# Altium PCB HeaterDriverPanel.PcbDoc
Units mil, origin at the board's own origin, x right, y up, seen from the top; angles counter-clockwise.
Board outline 14150 x 4775 mil, 6 copper layers (Top Layer, GND1, P, N, GND2, Bottom Layer), stack 62.668 mil thick; 0 components, 0 nets, 30 pads, 0 vias.
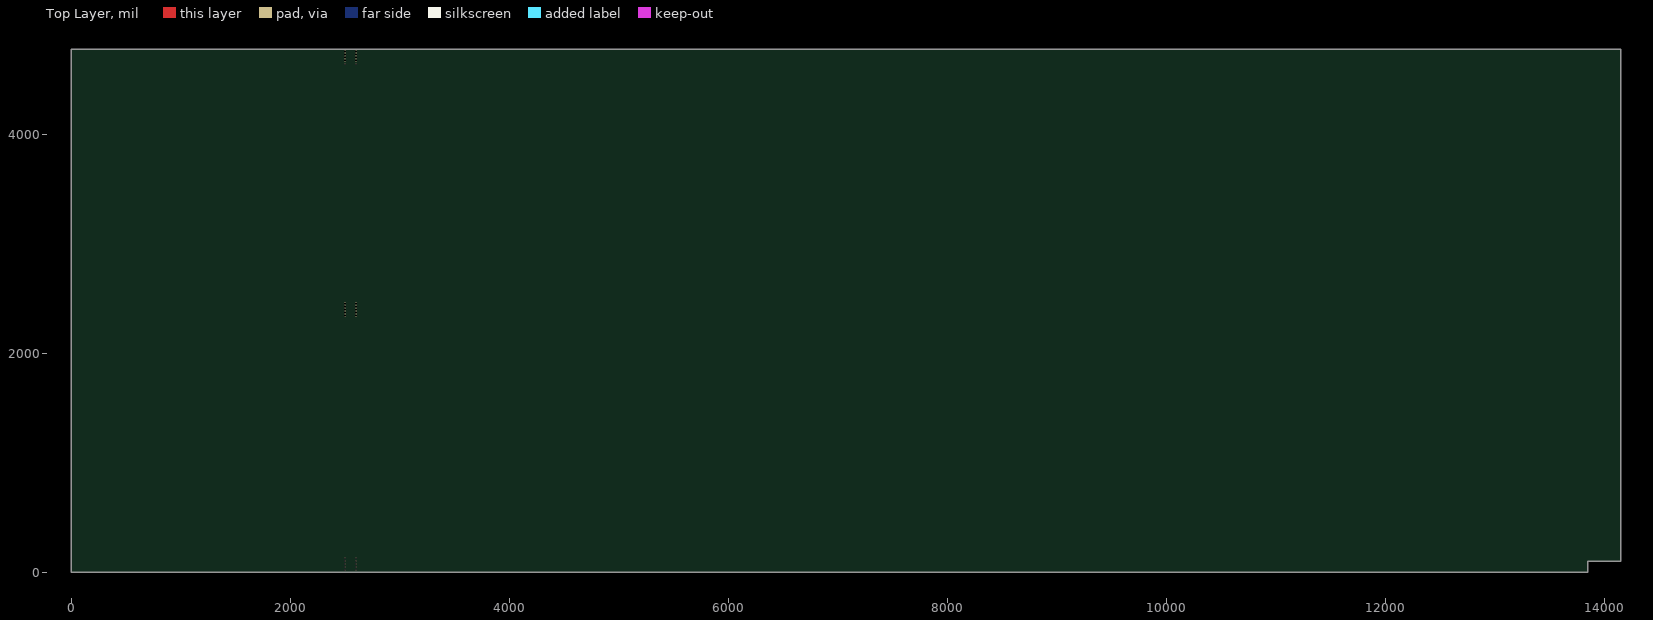
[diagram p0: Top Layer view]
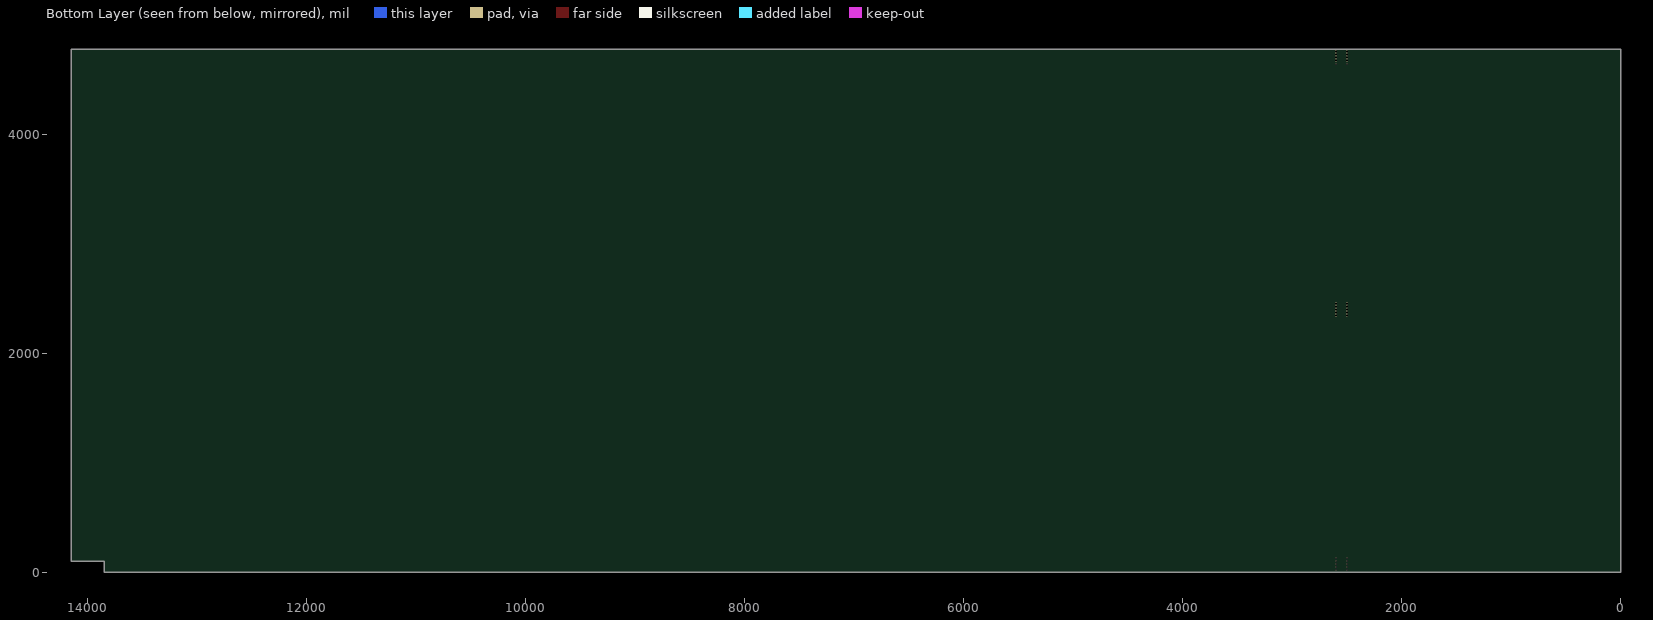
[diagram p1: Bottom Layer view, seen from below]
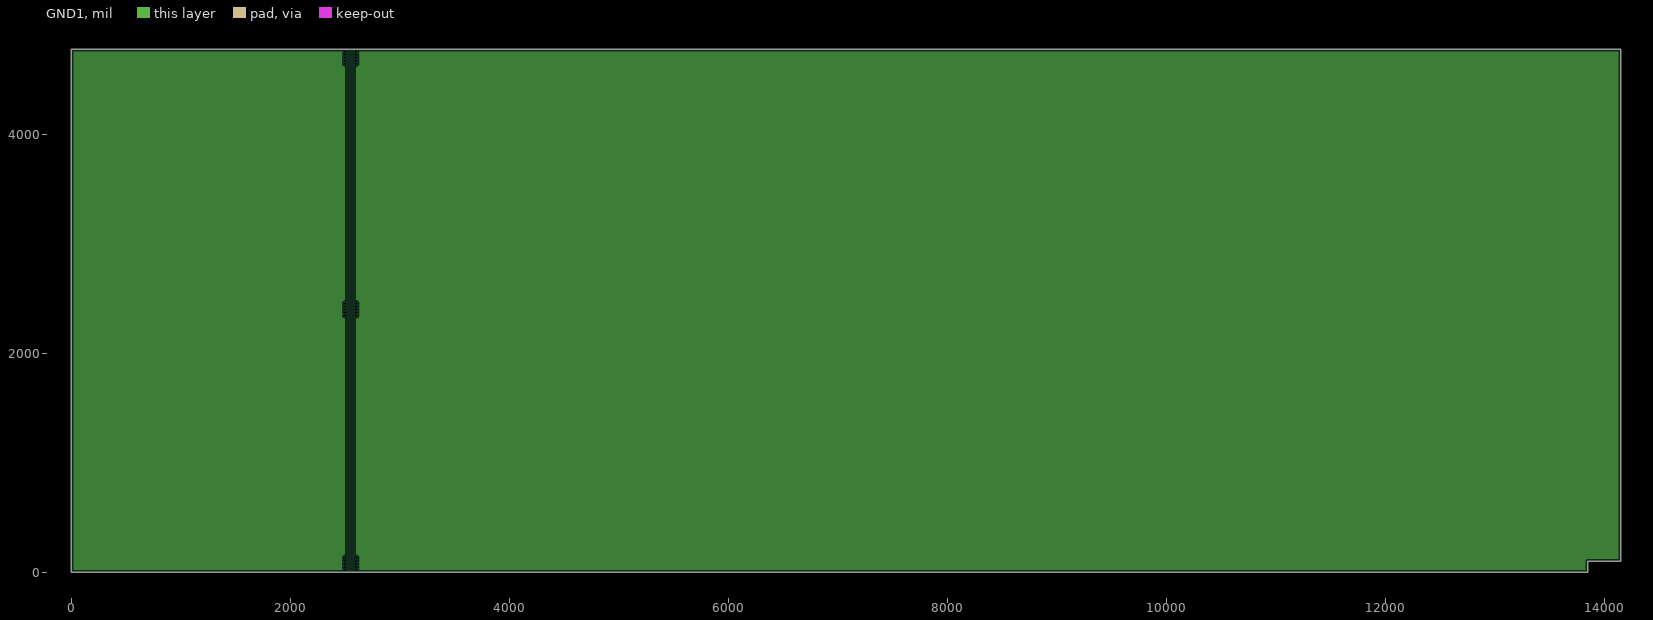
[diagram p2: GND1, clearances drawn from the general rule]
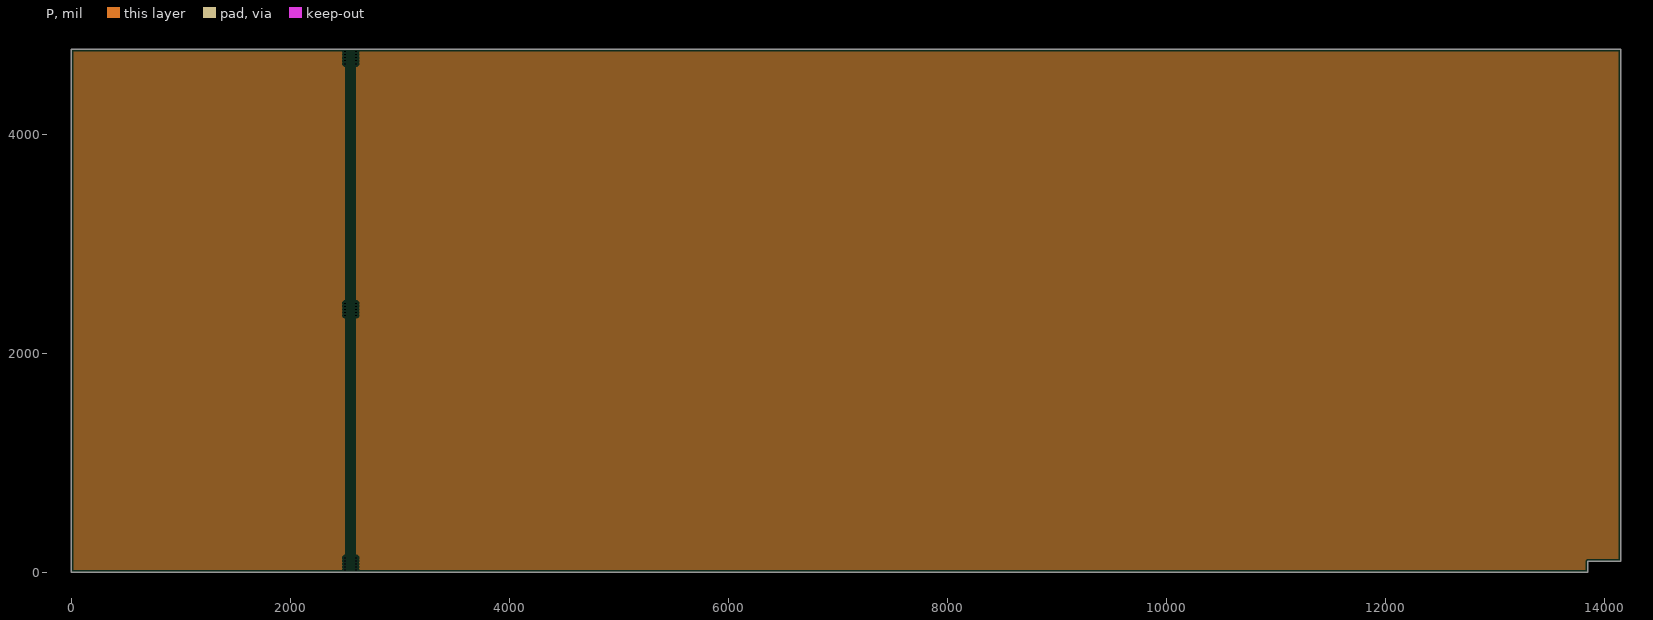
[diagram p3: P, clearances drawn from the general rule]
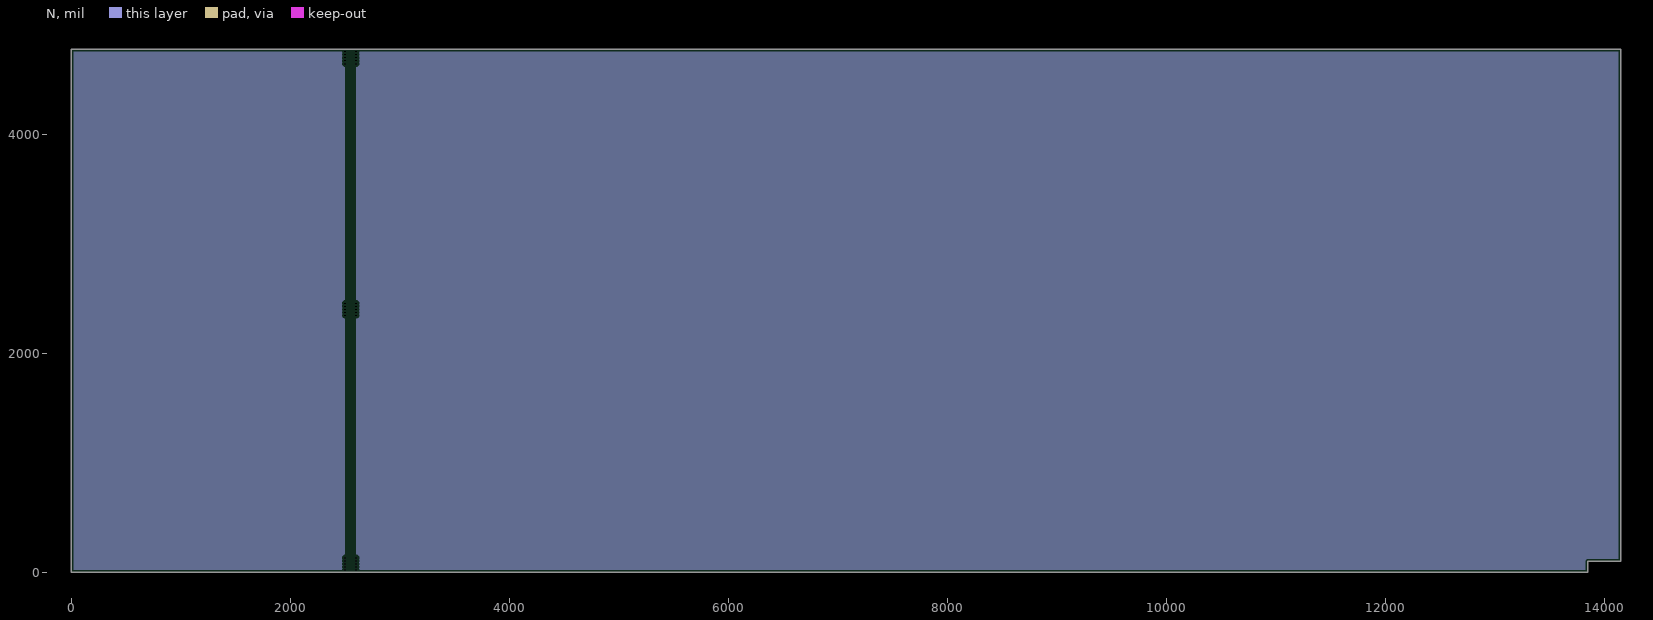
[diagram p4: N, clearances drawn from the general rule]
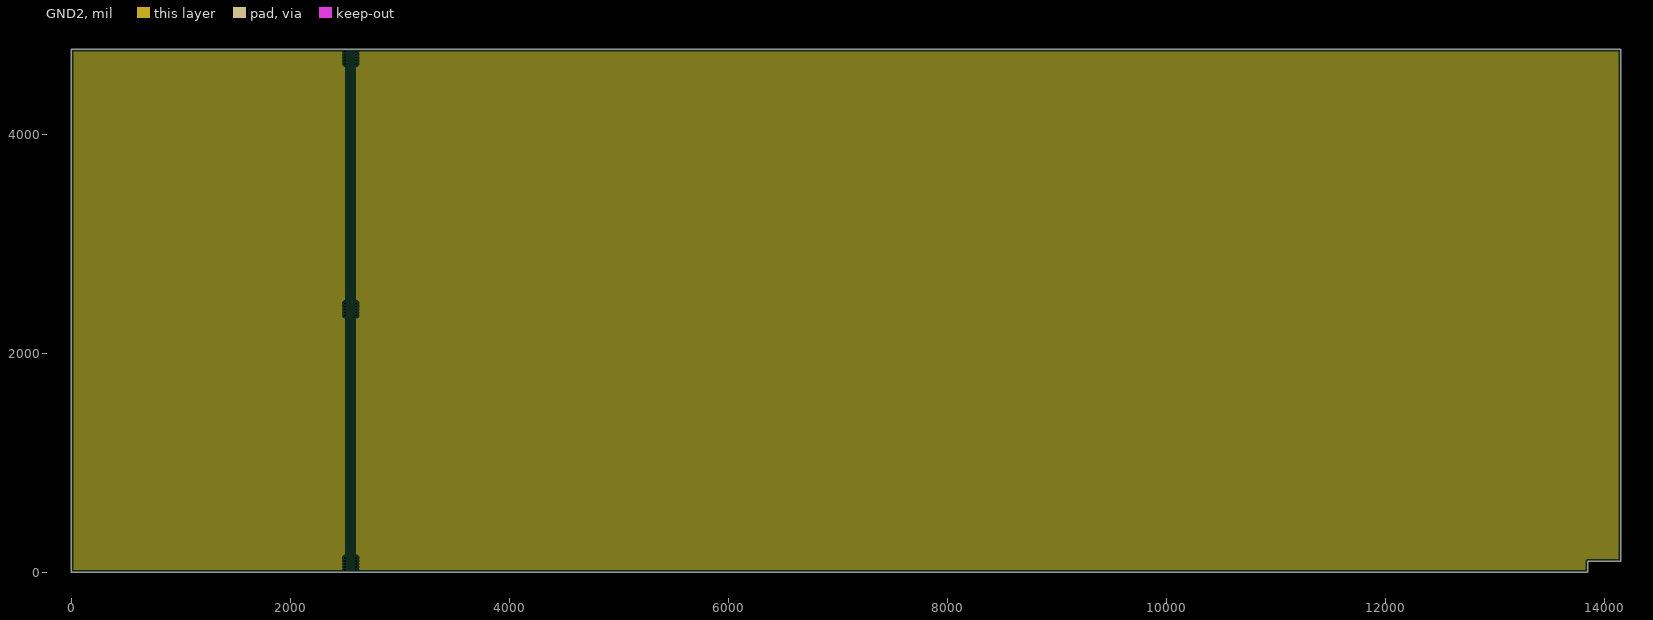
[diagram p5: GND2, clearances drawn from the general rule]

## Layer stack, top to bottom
Top Solder: solder mask 1, Solder Resist, Dk 3.5
Top Layer: signal copper 2.4
Dielectric 1: prepreg 2.8, PP-006, Dk 4.1
GND1: plane copper 1.417
Dielectric 2: core 21, Core-037, Dk 4.8
P: plane copper 1.417
Dielectric 3: prepreg 4.6, PP-016, Dk 4.4
N: plane copper 1.417
Dielectric 4: core 21, Core-037, Dk 4.8
GND2: plane copper 1.417
Dielectric 5: prepreg 2.8, PP-006, Dk 4.1
Bottom Layer: signal copper 2.4
Bottom Solder: solder mask 1, Solder Resist, Dk 3.5

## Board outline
0,0 0,4775 14150,4775 14150,100 13850,100 13850,0

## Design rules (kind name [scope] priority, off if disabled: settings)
Clearance [All] p1: gap=10 ignorepadtopadclearanceinfootprint=FALSE
PlaneClearance [All] p1: clearance=20
PlaneConnect [All] p1: planeconnectstyle=Relief reliefexpansion=20 reliefentries=4 reliefconductorwidth=10 reliefairgap=10
PolygonConnect [All] p1: connectstyle=Relief reliefconductorwidth=10 reliefentries=4 polygonreliefangle="90 Angle" airgapwidth=10
RoutingVias [All] p1: holewidth=28 width=50 viastyle="Through Hole" minholewidth=28 minwidth=50 maxholewidth=28 maxwidth=50
SolderMaskExpansion [All] p1: expansion=4 istentingtop=FALSE
Width [All] p1: maxlimit=10 minlimit=10 preferedwidth=10
28 further rules are at their usual default settings.

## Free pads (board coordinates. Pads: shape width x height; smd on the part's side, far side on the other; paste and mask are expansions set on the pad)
  round 18 hole 18 unplated mask+0: 0(2500,19) 0(2500,47) 0(2500,75) 0(2500,103) 0(2500,131) 0(2500,2344) 0(2500,2372) 0(2500,2400) 0(2500,2428) 0(2500,2456) 0(2500,4644) 0(2500,4672) 0(2500,4700) 0(2500,4728) 0(2500,4756) 0(2600,19) 0(2600,47) 0(2600,75) 0(2600,103) 0(2600,131) 0(2600,2344) 0(2600,2372) 0(2600,2400) 0(2600,2428) 0(2600,2456) 0(2600,4644) 0(2600,4672) 0(2600,4700) 0(2600,4728) 0(2600,4756)

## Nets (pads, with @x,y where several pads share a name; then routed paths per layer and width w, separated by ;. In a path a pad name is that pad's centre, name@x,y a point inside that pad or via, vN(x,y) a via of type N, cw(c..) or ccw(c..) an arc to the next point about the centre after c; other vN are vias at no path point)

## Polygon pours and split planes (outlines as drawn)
no net on GND1 (split plane): 2499.92,20.1 20.1,20.1 20.1,4754.9 2499.92,4754.9
no net on GND1 (split plane): 14129.9,120.1 13850,120.1 13846.08,119.71 13842.31,118.57 13838.83,116.71 13835.79,114.21 13833.29,111.17 13831.43,107.69 13830.29,103.92 13829.9,100 13829.9,20.1 2600.08,20.1 2600.08,4754.9 14129.9,4754.9
no net on P (split plane): 2499.92,20.1 20.1,20.1 20.1,4754.9 2499.92,4754.9
no net on P (split plane): 14129.9,120.1 13850,120.1 13846.08,119.71 13842.31,118.57 13838.83,116.71 13835.79,114.21 13833.29,111.17 13831.43,107.69 13830.29,103.92 13829.9,100 13829.9,20.1 2600.08,20.1 2600.08,4754.9 14129.9,4754.9
no net on N (split plane): 2499.92,20.1 20.1,20.1 20.1,4754.9 2499.92,4754.9
no net on N (split plane): 14129.9,120.1 13850,120.1 13846.08,119.71 13842.31,118.57 13838.83,116.71 13835.79,114.21 13833.29,111.17 13831.43,107.69 13830.29,103.92 13829.9,100 13829.9,20.1 2600.08,20.1 2600.08,4754.9 14129.9,4754.9
no net on GND2 (split plane): 2499.92,20.1 20.1,20.1 20.1,4754.9 2499.92,4754.9
no net on GND2 (split plane): 14129.9,120.1 13850,120.1 13846.08,119.71 13842.31,118.57 13838.83,116.71 13835.79,114.21 13833.29,111.17 13831.43,107.69 13830.29,103.92 13829.9,100 13829.9,20.1 2600.08,20.1 2600.08,4754.9 14129.9,4754.9

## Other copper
GND1 (plane layer: these items are gaps in the copper):
  lines w100: 2550,0 2550,4775
P (plane layer: these items are gaps in the copper):
  lines w100: 2550,0 2550,4775
N (plane layer: these items are gaps in the copper):
  lines w100: 2550,0 2550,4775
GND2 (plane layer: these items are gaps in the copper):
  lines w100: 2550,0 2550,4775

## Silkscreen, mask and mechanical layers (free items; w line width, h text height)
Mechanical 1:
  lines w10: 0,0 13850,0 ; 0,0 0,4775 ; 0,0 2500,0 2500,4775 0,4775 ; 0,4775 14150,4775 ; 13850,0 13850,100 14150,100 14150,4775 ; 13850,0 2600,0 2600,4775 14150,4775
Route Tool Path:
  lines w100: 2550,175 2550,2300 ; 2550,2500 2550,4600
Drill Drawing:
  drawing of 157 lines, arcs and shapes, not listed
  text "Symbol" at 97.5,7952.5 h72
  text "Count" at 603.38,7952.5 h72
  text "Hole Size" at 1203.22,7952.5 h72
  text "Plated" at 2352.88,7952.5 h72
  text "Hole Type" at 2858.76,7952.5 h72
  text "Drill Layer Pair" at 3592.56,7952.5 h72
  text "Via/Pad" at 5092.11,7952.5 h72
  text "Pad Shape" at 5681.96,7952.5 h72
  text "Template" at 6427.76,7952.5 h72
  text "Description" at 7117.57,7952.5 h72
  text "Hole Tolerance (+)" at 7971.33,7952.5 h72
  text "Hole Tolerance (-)" at 9304.94,7952.5 h72
  text "2" at 603.38,7802.5 h60
  text "75.00mil (1.905mm)" at 1203.22,7802.5 h60
  text "PTH" at 2352.88,7802.5 h60
  text "Round" at 2858.76,7802.5 h60
  text "Top Layer - Bottom Layer" at 3592.56,7802.5 h60
  text "Pad" at 5092.11,7802.5 h60
  text "Rounded" at 5681.96,7802.5 h60
  text "c254h190" at 6427.76,7802.5 h60
  text "2" at 603.38,7652.5 h60
  text "155.00mil (3.937mm)" at 1203.22,7652.5 h60
  text "PTH" at 2352.88,7652.5 h60
  text "Round" at 2858.76,7652.5 h60
  text "Top Layer - Bottom Layer" at 3592.56,7652.5 h60
  text "Pad" at 5092.11,7652.5 h60
  text "Rounded" at 5681.96,7652.5 h60
  text "c508h394" at 6427.76,7652.5 h60
  text "4" at 603.38,7502.5 h60
  text "29.00mil (0.737mm)" at 1203.22,7502.5 h60
  text "PTH" at 2352.88,7502.5 h60
  text "Round" at 2858.76,7502.5 h60
  text "Top Layer - Bottom Layer" at 3592.56,7502.5 h60
  text "Pad" at 5092.11,7502.5 h60
  text "Rounded" at 5681.96,7502.5 h60
  text "c120h74" at 6427.76,7502.5 h60
  text "4" at 603.38,7352.5 h60
  text "128.35mil (3.260mm)" at 1203.22,7352.5 h60
  text "PTH" at 2352.88,7352.5 h60
  text "Round" at 2858.76,7352.5 h60
  text "Top Layer - Bottom Layer" at 3592.56,7352.5 h60
  text "Pad" at 5092.11,7352.5 h60
  text "Rounded" at 5681.96,7352.5 h60
  text "c476h326" at 6427.76,7352.5 h60
  text "4" at 603.38,7202.5 h60
  text "190.00mil (4.826mm)" at 1203.22,7202.5 h60
  text "PTH" at 2352.88,7202.5 h60
  text "Round" at 2858.76,7202.5 h60
  text "Top Layer - Bottom Layer" at 3592.56,7202.5 h60
  text "Pad" at 5092.11,7202.5 h60
  text "Rounded" at 5681.96,7202.5 h60
  text "c559h483" at 6427.76,7202.5 h60
  text "4" at 603.38,7052.5 h60
  text "193.00mil (4.902mm)" at 1203.22,7052.5 h60
  text "PTH" at 2352.88,7052.5 h60
  text "Round" at 2858.76,7052.5 h60
  text "Top Layer - Bottom Layer" at 3592.56,7052.5 h60
  text "Pad" at 5092.11,7052.5 h60
  text "Rounded" at 5681.96,7052.5 h60
  text "c584h490" at 6427.76,7052.5 h60
  text "8" at 603.38,6902.5 h60
  text "28.00mil (0.711mm)" at 1203.22,6902.5 h60
  text "PTH" at 2352.88,6902.5 h60
  text "Round" at 2858.76,6902.5 h60
  text "Top Layer - Bottom Layer" at 3592.56,6902.5 h60
  text "Pad" at 5092.11,6902.5 h60
  text "Rounded" at 5681.96,6902.5 h60
  text "c122h71" at 6427.76,6902.5 h60
  text "8" at 603.38,6752.5 h60
  text "32.00mil (0.813mm)" at 1203.22,6752.5 h60
  text "PTH" at 2352.88,6752.5 h60
  text "Round" at 2858.76,6752.5 h60
  text "Top Layer - Bottom Layer" at 3592.56,6752.5 h60
  text "Pad" at 5092.11,6752.5 h60
  text "(Mixed)" at 5681.96,6752.5 h60
  text "(Mixed)" at 6427.76,6752.5 h60
  text "9" at 603.38,6602.5 h60
  text "40.00mil (1.016mm)" at 1203.22,6602.5 h60
  text "PTH" at 2352.88,6602.5 h60
  text "Round" at 2858.76,6602.5 h60
  text "Top Layer - Bottom Layer" at 3592.56,6602.5 h60
  text "Pad" at 5092.11,6602.5 h60
  text "(Mixed)" at 5681.96,6602.5 h60
  text "(Mixed)" at 6427.76,6602.5 h60
  text "18" at 603.38,6452.5 h60
  text "42.91mil (1.090mm)" at 1203.22,6452.5 h60
  text "PTH" at 2352.88,6452.5 h60
  text "Round" at 2858.76,6452.5 h60
  text "Top Layer - Bottom Layer" at 3592.56,6452.5 h60
  text "Pad" at 5092.11,6452.5 h60
  text "(Mixed)" at 5681.96,6452.5 h60
  text "(Mixed)" at 6427.76,6452.5 h60
  text "18" at 603.38,6302.5 h60
  text "52.00mil (1.321mm)" at 1203.22,6302.5 h60
  text "PTH" at 2352.88,6302.5 h60
  text "Round" at 2858.76,6302.5 h60
  text "Top Layer - Bottom Layer" at 3592.56,6302.5 h60
  text "Pad" at 5092.11,6302.5 h60
  text "Rounded" at 5681.96,6302.5 h60
  text "c190h132" at 6427.76,6302.5 h60
  text "30" at 603.38,6152.5 h60
  text "18.00mil (0.457mm)" at 1203.22,6152.5 h60
  text "NPTH" at 2352.88,6152.5 h60
  text "Round" at 2858.76,6152.5 h60
  text "Top Layer - Bottom Layer" at 3592.56,6152.5 h60
  text "Pad" at 5092.11,6152.5 h60
  text "Rounded" at 5681.96,6152.5 h60
  text "c46hn46m46" at 6427.76,6152.5 h60
  text "A" at 68.41,6142.51 h66.67
  text "34" at 603.38,6002.5 h60
  text "80.00mil (2.032mm)" at 1203.22,6002.5 h60
  text "PTH" at 2352.88,6002.5 h60
  text "Round" at 2858.76,6002.5 h60
  text "Top Layer - Bottom Layer" at 3592.56,6002.5 h60
  text "Pad" at 5092.11,6002.5 h60
  text "(Mixed)" at 5681.96,6002.5 h60
  text "(Mixed)" at 6427.76,6002.5 h60
  text "54" at 603.38,5852.5 h60
  text "20.00mil (0.508mm)" at 1203.22,5852.5 h60
  text "PTH" at 2352.88,5852.5 h60
  text "Round" at 2858.76,5852.5 h60
  text "Top Layer - Bottom Layer" at 3592.56,5852.5 h60
  text "Via" at 5092.11,5852.5 h60
  text "Rounded" at 5681.96,5852.5 h60
  text "v94h51" at 6427.76,5852.5 h60
  text "149" at 603.38,5702.5 h60
  text "14.00mil (0.356mm)" at 1203.22,5702.5 h60
  text "PTH" at 2352.88,5702.5 h60
  text "Round" at 2858.76,5702.5 h60
  text "Top Layer - Bottom Layer" at 3592.56,5702.5 h60
  text "(Mixed)" at 5092.11,5702.5 h60
  text "Rounded" at 5681.96,5702.5 h60
  text "(Mixed)" at 6427.76,5702.5 h60
  text "348 Total" at 603.38,5552.5 h60

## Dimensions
13850,100 to 14150,100 on Dimensions
13850,100 to 13850,0 on Dimensions
0,4775 to 14150,4775 on Dimensions
2500,4775 to 2600,4775 on Dimensions
2600,4775 to 14150,4775 on Dimensions
0,4775 to 2500,4775 on Dimensions
0,0 to 0,4775 on Dimensions

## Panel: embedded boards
"..\FusedPowerProtection\FusedPowerProtection.PcbDoc" at 2500,0, 1 rows x 1 columns, spacing 2500 x 1500, rotation 90
"..\HeaterDriver\HeaterContollerDriver.PcbDoc" at 2600,0, 1 rows x 1 columns, spacing 2500 x 1500, rotation 0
